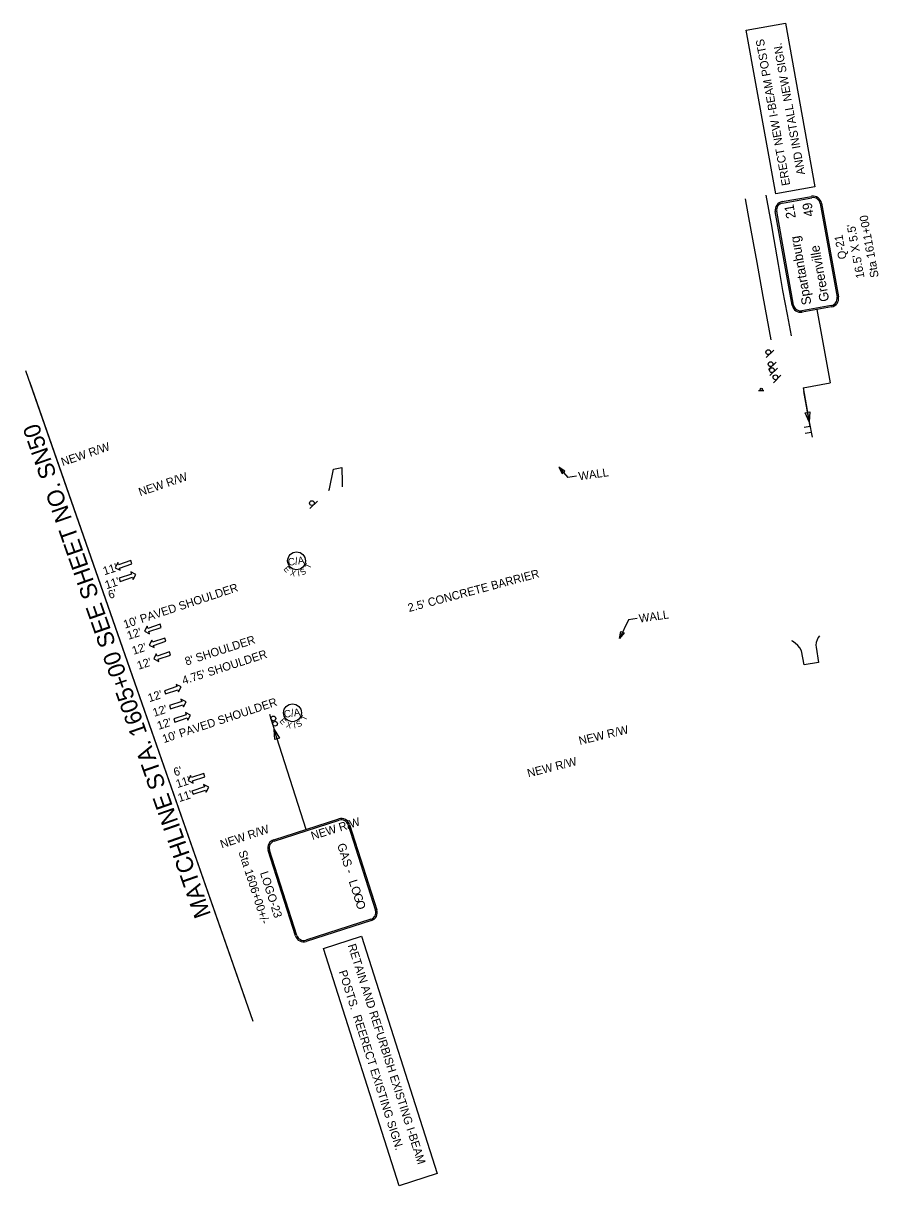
# Model space of a CAD drawing. Extents: x 1807400 to 1809002, y 1189416 to 1190516.
# Drawn here: x 1807400 to 1808120, y 1189416 to 1190396 of the extents above; entities that cross this region are included whole.
import ezdxf

# ---------------------------------------------------------------- set-up
doc = ezdxf.new("R2010")
doc.units = 0
for name, color, linetype in [('RD_EX_Road', 7, 'Continuous'), ('RD_PD_Final_LnLine', 7, 'Continuous'), ('RD_PD_Final_TX', 7, 'Continuous'), ('RD_PD_RW_TX', 7, 'Continuous'), ('RD_SHT_MatchLine', 7, 'Continuous'), ('RD_SHT_TX', 7, 'Continuous'), ('RD_Sketch8', 7, 'Continuous'), ('SN_P_Signs', 7, 'Continuous'), ('TERMINATOR', 7, 'Continuous')]:
    doc.layers.add(name, color=color, linetype=linetype)

# ---------------------------------------------------------------- blocks, each defined once
blk = doc.blocks.new('SARRW2')
at = {"layer": 'RD_PD_Final_LnLine'}
blk.add_lwpolyline([(-12, 1.2), (-12, -1.2), (-2.83, -1.2), (-2.83, -2.83), (0, 0), (-2.83, 2.83), (-2.83, 1.2)], close=True, dxfattribs=at)

msp = doc.modelspace()

# ---------------------------------------------------------------- linework, layer by layer
at = {"layer": 'RD_EX_Road'}
for points in [[(1808024.94, 1190251.12), (1808029.48, 1190226.95), (1808031.75, 1190213.82), (1808035.5, 1190192.71), (1808039.01, 1190170.72), (1808043.01, 1190150.44), (1808046.37, 1190132.45)], [(1808007.7, 1190248.02), (1808010, 1190235.44), (1808014.44, 1190210.93), (1808017.41, 1190194.43), (1808022.45, 1190165.56), (1808029.21, 1190129.25)], [(1807656.99, 1190002.11), (1807657.56, 1190003.69), (1807660.8, 1190020.13), (1807667.78, 1190021.47), (1807668.04, 1190008.84), (1807668.07, 1190006.4), (1807668.25, 1190005.36)], [(1808070.32, 1189879.74), (1808069.18, 1189878.22), (1808068.17, 1189876.22), (1808067.53, 1189874.07), (1808067.27, 1189871.84), (1808067.32, 1189870.22), (1808069.28, 1189857.22), (1808057.24, 1189855.08), (1808055.17, 1189867.09), (1808053.71, 1189869.46), (1808051.93, 1189871.61), (1808049.86, 1189873.48), (1808047.55, 1189875.04), (1808047.05, 1189875.31)]]:
    msp.add_lwpolyline(points, dxfattribs=at)
at = {"layer": 'RD_PD_Final_TX'}
for p, q in [((1807850.53, 1190021.91), (1807858.31, 1190013.08)), ((1807865.68, 1190014.13), (1807858.31, 1190013.08)), ((1807909.21, 1189893.22), (1807901.74, 1189877.33)), ((1807916.57, 1189894.27), (1807909.21, 1189893.22))]:
    msp.add_line(p, q, dxfattribs=at)
at = {"layer": 'RD_SHT_MatchLine'}
for p, q in [((1807401.54, 1190103.4), (1807592.82, 1189554.76)), ((1807404.78, 1190094.1), (1807586.05, 1189574.17))]:
    msp.add_line(p, q, dxfattribs=at)
at = {"layer": 'RD_Sketch8'}
for centre in [(1807629.73, 1189942.89), (1807626.34, 1189814.78)]:
    msp.add_circle(centre, 7.5, dxfattribs=at)
at = {"layer": 'SN_P_Signs'}
for p, q in [((1808008.49, 1190390.06), (1808041.57, 1190396.02)), ((1808033.33, 1190252.26), (1808008.49, 1190390.06)), ((1808041.57, 1190396.02), (1808066.42, 1190258.22)), ((1808066.42, 1190258.22), (1808033.33, 1190252.26)), ((1808047.24, 1190158.28), (1808032.99, 1190237.29)), ((1808048.42, 1190158.5), (1808034.17, 1190237.5)), ((1808068, 1190154.71), (1808079.16, 1190092.8)), ((1808025.38, 1190114.15), (1808031.74, 1190120.51)), ((1808027.28, 1190104.04), (1808033.64, 1190110.4)), ((1808028.37, 1190098.98), (1808034.74, 1190105.34)), ((1808031.38, 1190092.94), (1808037.75, 1190099.3)), ((1808018.97, 1190086.36), (1808023.47, 1190086.36)), ((1808056.42, 1190088.7), (1808079.16, 1190092.8)), ((1808056.42, 1190088.7), (1808061.61, 1190059.9)), ((1808062.31, 1190056.05), (1808056.96, 1190085.73)), ((1808062.31, 1190056.05), (1808057.4, 1190055.16)), ((1808061.61, 1190059.9), (1808063.93, 1190047.06)), ((1808063.2, 1190051.11), (1808058.29, 1190050.23)), ((1807640.91, 1189986.87), (1807647.28, 1189993.24)), ((1807606.87, 1189813.69), (1807609.61, 1189805.12)), ((1807608.28, 1189809.29), (1807611.02, 1189800.72)), ((1807637.92, 1189716.54), (1807611.02, 1189800.72)), ((1807652.35, 1189616.16), (1807684.37, 1189626.39)), ((1807684.37, 1189626.39), (1807748.29, 1189426.34)), ((1807716.27, 1189416.1), (1807652.35, 1189616.16)), ((1807748.29, 1189426.34), (1807716.27, 1189416.1))]:
    msp.add_line(p, q, dxfattribs=at)
for points in [[(1808038.8, 1190245.65), (1808063.6, 1190250.12)], [(1808039.01, 1190244.47), (1808063.81, 1190248.94)], [(1808070.78, 1190244.1), (1808085.03, 1190165.1)], [(1808071.97, 1190244.32), (1808086.21, 1190165.31)], [(1808080.19, 1190158.13), (1808055.39, 1190153.66)], [(1808080.4, 1190156.95), (1808055.6, 1190152.47)], [(1807610.48, 1189707.78), (1807665.35, 1189725.31)], [(1807610.85, 1189706.63), (1807665.71, 1189724.16)], [(1807673.26, 1189720.28), (1807696.27, 1189648.26)], [(1807674.4, 1189720.64), (1807697.41, 1189648.63)], [(1807628.83, 1189626.71), (1807605.82, 1189698.73)], [(1807629.97, 1189627.08), (1807606.96, 1189699.09)], [(1807692.38, 1189640.72), (1807637.51, 1189623.19)], [(1807692.74, 1189639.58), (1807637.88, 1189622.05)]]:
    msp.add_lwpolyline(points, dxfattribs=at)
for points in [[(1808062.18, 1190068.33), (1808061.61, 1190059.9), (1808058.14, 1190067.61)], [(1807611.56, 1189792.28), (1807611.02, 1189800.72), (1807615.47, 1189793.53)]]:
    msp.add_lwpolyline(points, close=True, dxfattribs=at)
for centre, radius in [((1808027.14, 1190118.78), 2), ((1808029.04, 1190108.66), 2), ((1808030.14, 1190103.6), 2), ((1808033.15, 1190097.57), 2), ((1808021.23, 1190087.37), 1), ((1807642.68, 1189991.5), 2), ((1807610.18, 1189810.01), 2), ((1807611.58, 1189805.6), 2)]:
    msp.add_circle(centre, radius, dxfattribs=at)
for centre, radius, start, end in [((1808040.08, 1190238.57), 7.2, 100.22067, 190.22067), ((1808040.08, 1190238.57), 6, 100.22067, 190.22067), ((1808064.88, 1190243.04), 7.2, 10.22067, 100.22067), ((1808064.88, 1190243.04), 6, 10.22067, 100.22067), ((1808079.12, 1190164.03), 6, 280.22067, 10.22067), ((1808079.12, 1190164.03), 7.2, 280.22067, 10.22067), ((1808054.32, 1190159.56), 7.2, 190.22067, 280.22067), ((1808054.32, 1190159.56), 6, 190.22067, 280.22067), ((1807667.54, 1189718.45), 7.2, 17.72067, 107.72067), ((1807667.54, 1189718.45), 6, 17.72067, 107.72067), ((1807612.67, 1189700.92), 7.2, 107.72067, 197.72067), ((1807612.67, 1189700.92), 6, 107.72067, 197.72067), ((1807690.55, 1189646.44), 6, 287.72067, 17.72067), ((1807690.55, 1189646.44), 7.2, 287.72067, 17.72067), ((1807635.68, 1189628.9), 7.2, 197.72067, 287.72067), ((1807635.68, 1189628.9), 6, 197.72067, 287.72067)]:
    msp.add_arc(centre, radius, start, end, dxfattribs=at)
at = {"layer": 'TERMINATOR'}
for points in [[(1807855.62, 1190018.4), (1807850.53, 1190021.91), (1807853.37, 1190016.42)], [(1807905.65, 1189882.13), (1807901.74, 1189877.33), (1807902.94, 1189883.4)]]:
    msp.add_lwpolyline(points, close=True, dxfattribs=at)

# ---------------------------------------------------------------- block references
at = {"layer": 'RD_PD_Final_LnLine'}
for p, xscale, yscale, rotation in [((1807476.92, 1189937.09), 1.1999999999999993, 1.2000000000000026, -161.5277674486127), ((1807494.34, 1189931.47), 1.1999999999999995, 1.2000000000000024, 18.472232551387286), ((1807501.66, 1189883.48), 1.1999999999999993, 1.2000000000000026, -161.5277674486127), ((1807505.56, 1189871.83), 1.1999999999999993, 1.2000000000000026, -161.5277674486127), ((1807509.45, 1189860.18), 1.1999999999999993, 1.2000000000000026, -161.5277674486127), ((1807532.5, 1189836.61), 1.1999999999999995, 1.2000000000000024, 18.472232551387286), ((1807536.7, 1189824.04), 1.1999999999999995, 1.2000000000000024, 18.472232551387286), ((1807540.44, 1189812.84), 1.1999999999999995, 1.2000000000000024, 18.472232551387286), ((1807538.35, 1189757.67), 1.1999999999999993, 1.2000000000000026, -161.5277674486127), ((1807555.77, 1189752.05), 1.1999999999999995, 1.2000000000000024, 18.472232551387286)]:
    msp.add_blockref('SARRW2', p, dxfattribs=dict(at, xscale=xscale, yscale=yscale, rotation=rotation))

# ---------------------------------------------------------------- texts
at = {"layer": 'RD_PD_Final_TX'}
for s, rotation, p in [('WALL', 8.10669, (1807867.78, 1190010.66)), ("11'", 17.76777, (1807467.93, 1189930.67)), ("11'", 17.76777, (1807469.6, 1189918.9)), ("2.5' CONCRETE BARRIER", 14.95567, (1807724.54, 1189899.68)), ("6'", 16.62166, (1807472.23, 1189910.7)), ("10' PAVED SHOULDER", 18.35833, (1807485.18, 1189885.66)), ('WALL', 8.10669, (1807918.67, 1189890.8)), ("12'", 17.84541, (1807488.19, 1189876.26)), ("8' SHOULDER", 17.92486, (1807537.01, 1189854.57)), ("12'", 17.76777, (1807492.42, 1189863.6)), ("12'", 17.84541, (1807496.62, 1189851.01)), ("4.75' SHOULDER", 17.92486, (1807534.56, 1189838.49)), ("12'", 17.76777, (1807505.75, 1189823.69)), ("12'", 17.76777, (1807509.87, 1189811.35)), ("10' PAVED SHOULDER", 18.35833, (1807518.04, 1189789.19)), ("12'", 17.76777, (1807513.54, 1189800.37)), ("6'", 16.62166, (1807527.3, 1189761.17)), ("11'", 17.76777, (1807529.36, 1189751.25)), ("11'", 17.76777, (1807531.03, 1189739.48))]:
    msp.add_text(s, height=7, rotation=rotation, dxfattribs=at).set_placement(p)
at = {"layer": 'RD_PD_RW_TX'}
for rotation, p in [(18.74381, (1807432.77, 1190022.65)), (18.74381, (1807498.09, 1189997.27)), (13.41245, (1807868.35, 1189787.69)), (14.28783, (1807825.03, 1189760.31)), (17.22933, (1807643.15, 1189707.5)), (18.44223, (1807566.78, 1189700.42))]:
    msp.add_text('NEW R/W', height=7, rotation=rotation, dxfattribs=at).set_placement(p)
at = {"layer": 'RD_SHT_TX'}
msp.add_text('MATCHLINE STA. 1605+00 SEE SHEET NO. SN50', height=14.1726, rotation=109.34465, dxfattribs=at).set_placement((1807557.81, 1189644.74))
at = {"layer": 'RD_Sketch8'}
for s, height, rotation, p in [('E', 5, 311.31793, (1807618.41, 1189935.71)), ('C/A', 6.25, 8.10669, (1807622.85, 1189938.6)), ('T', 5, 66.29183, (1807641.05, 1189935.71)), ('X', 5, 343.7473, (1807623.94, 1189930.78)), ('I', 5, 7.9073, (1807630.95, 1189929.69)), ('S', 5, 29.89913, (1807634.54, 1189930.37)), ('E', 5, 311.31793, (1807615.02, 1189807.59)), ('C/A', 6.25, 8.10669, (1807619.46, 1189810.49)), ('T', 5, 66.29183, (1807637.65, 1189807.6)), ('X', 5, 343.7473, (1807620.55, 1189802.67)), ('I', 5, 7.9073, (1807627.55, 1189801.58)), ('S', 5, 29.89913, (1807631.14, 1189802.26))]:
    msp.add_text(s, height=height, rotation=rotation, dxfattribs=at).set_placement(p)
at = {"layer": 'SN_P_Signs'}
for s, height, rotation, p in [('ERECT NEW I-BEAM POSTS', 6.9998, 100.22075, (1808045.56, 1190259.78)), ('AND INSTALL NEW SIGN.', 6.9998, 100.22075, (1808058.15, 1190268.85)), ('21', 8, 100.22067, (1808050.39, 1190232.12)), ('49', 8, 100.22067, (1808065.55, 1190233.66)), ('Sta 1611+00', 7, 100.22075, (1808120.17, 1190182.2)), ("16.5' X 5.5'", 7, 100.22075, (1808108.19, 1190181.61)), ('Spartanburg', 8, 100.22067, (1808063.51, 1190159.34)), ('Q-21', 7, 100.22075, (1808093.19, 1190197.72)), ('Greenville', 8, 100.22067, (1808078.47, 1190162.04)), ('GAS', 7.2, 287.72067, (1807663.81, 1189703.52)), ('Sta 1606+00+/-', 7, 287.72075, (1807580.71, 1189697.55)), ('-', 7.2, 287.72067, (1807670.78, 1189681.69)), ('-', 7.2, 287.72067, (1807670.78, 1189681.69)), ('LOGO-23', 7, 287.72075, (1807598.86, 1189679.86)), ('L', 7.2, 287.72067, (1807673.63, 1189672.77)), ('L', 7.2, 287.72067, (1807673.63, 1189672.77)), ('O', 7.2, 287.72067, (1807675.38, 1189667.3)), ('O', 7.2, 287.72067, (1807675.38, 1189667.3)), ('G', 7.2, 287.72067, (1807677.33, 1189661.19)), ('G', 7.2, 287.72067, (1807677.33, 1189661.19)), ('O', 7.2, 287.72067, (1807679.22, 1189655.3)), ('O', 7.2, 287.72067, (1807679.22, 1189655.3)), ('RETAIN AND REFURBISH EXISTING I-BEAM', 7, 287.72075, (1807672.78, 1189618.75)), ('POSTS.  REERECT EXISTING SIGN.', 7, 287.72075, (1807665.17, 1189596.58))]:
    msp.add_text(s, height=height, rotation=rotation, dxfattribs=at).set_placement(p)

doc.saveas('drawing.dxf')
